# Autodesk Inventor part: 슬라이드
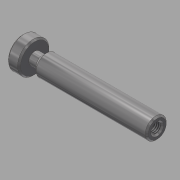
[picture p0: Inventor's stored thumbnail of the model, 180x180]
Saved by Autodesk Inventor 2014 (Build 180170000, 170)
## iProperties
Created: 2015-12
Part Number: 슬라이드
Document SubType Name: Modeling
Designer: mdu
Density: 8.08 g/cm^3
Material: 스테인리스강
Appearance: 반광택
Author: mdu
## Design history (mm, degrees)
sketch "스케치1"
  geometry: L1 (-45, 0)-(45, 0); L2 (-45, 0)-(-45, 10.5); L3 (-45, 10.5)-(-37, 10.5); L4 (-37, 10.5)-(-37, 4); L5 (-37, 4)-(-32, 4); L6 (-32, 4)-(-29, 7); L7 (-29, 7)-(45, 7); L8 (45, 7)-(45, 0); 2 further points
  constraints: 16 end point, 4 parallel, 2 perpendicular, 1 coincident, 1 horizontal, 1 midpoint
  dimensions: "d0" = 90 distance of L1.start L1.end; "d1" = 21 diameter of L3 L1; "d2" = 14 diameter of L7 L1; "d3" = 8 diameter of L5 L1; "d4" = 8 distance of L2.end L3.end; "d5" = 5 distance of L4.end L5.end; "d6" = 135 deg angle of L6 L5
revolve "회전1" sketch "스케치1" stored, may be unused: angle "d7" = 90 deg
chamfer "모따기1" distance "d8" = 1; stored, may be unused: second distance "d9" = 2, angle "d10" = 45 deg
hole "구멍1" diameter "d13" = 6.647; stored, may be unused: countersink angle "d17" = 90 deg, drill point angle "d19" = 118 deg; dims "d11" = 10, "d12" = 10, "d14" = 9, "d15" = 4, "d16" = 2, "d18" = 12
chamfer "모따기2" distance "d20" = 1; stored, may be unused: second distance "d21" = 2, angle "d22" = 45 deg
node "솔리드1"
